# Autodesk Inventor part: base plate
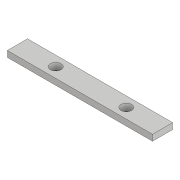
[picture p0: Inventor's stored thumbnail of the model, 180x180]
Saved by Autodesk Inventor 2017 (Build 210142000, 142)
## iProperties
Created: 2016-03
Part Number: base plate
Material: Generic
Document SubType Name: Modeling
Designer: Sandeep
Density: 1 g/cm^3
Appearance: Default
Author: Sandeep
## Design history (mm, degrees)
sketch "Sketch1"
  geometry: L1 (0, 0)-(144, 0); L2 (144, 0)-(144, 20); L3 (144, 20)-(0, 20); L4 (0, 20)-(0, 0)
  constraints: 8 end point, 2 parallel, 1 horizontal, 1 perpendicular
  dimensions: "d0" = 144 distance of L1.start L1.end; "d1" = 20 distance of L1.end L2.end
extrude "Extrusion1" new body sketch "Sketch1" distance "d2" = 6; taper "d3" = 0 deg
sketch "Sketch2"
  geometry: L1 (0, 20)-(0, 0) reference; L2 (0, 10)-(181.292, 10); 2 further points
  constraints: 2 end point, 2 point on line, 1 horizontal, 1 midpoint
  dimensions: "d4" = 70 distance of point (108, 10) point (38, 10); "d5" = 38 distance from line of L1 point (38, 10)
hole "Hole1" sketch "Sketch2" at (38, 10), (108, 10) diameter "d6" = 6; stored, may be unused: countersink angle "d10" = 45 deg, drill point angle "d12" = 118 deg; dims "d7" = 6, "d8" = 10.5, "d9" = 2, "d11" = 8
body "Solid1"
